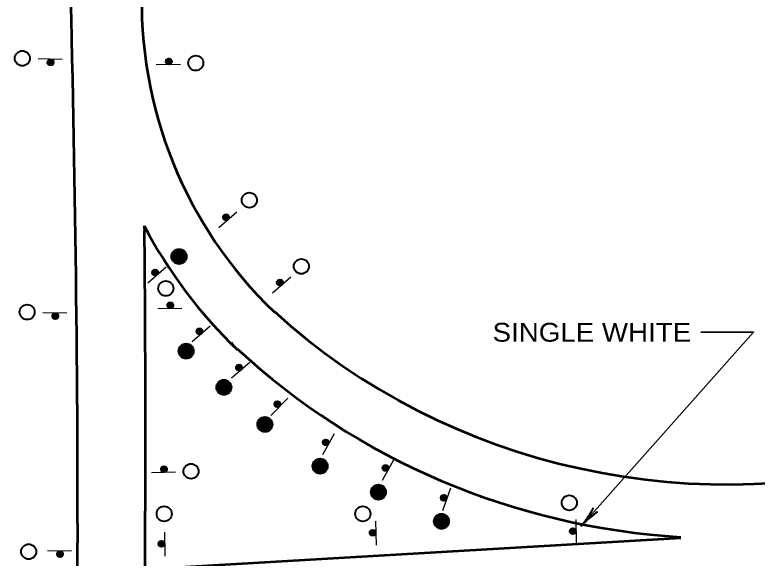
# Model space of a CAD drawing. Extents: x 393 to 1249, y -102 to 530.
# Drawn here: x 863.4 to 959.2, y 159 to 229.1 of the extents above; entities that cross this region are included whole.
import ezdxf
from ezdxf.enums import TextEntityAlignment as Align

# ---------------------------------------------------------------- set-up
doc = ezdxf.new("R2010")
doc.units = 0
doc.header["$LTSCALE"] = 0.97
doc.layers.add('1', color=7, linetype='Continuous', lineweight=40)
doc.layers.add('4', color=7, linetype='Continuous', lineweight=25)

msp = doc.modelspace()

# ---------------------------------------------------------------- linework, layer by layer
at = {"layer": '1', "lineweight": 53}
msp.add_line((880.2188, 157.5822), (949.3432, 161.6421), dxfattribs=at)
at = {"layer": '1', "lineweight": 35}
msp.add_lwpolyline([(951.9086, 188.1491), (958.7126, 188.1491), (936.4571, 163.1419)], dxfattribs=at)
at = {"layer": '1'}
for centre, radius in [((864.3972, 223.4812), 0.972), ((868.0362, 222.96), 0.3791), ((868.0164, 222.9409), 0.3402), ((868.046, 222.9696), 0.35), ((868.0459, 222.9598), 0.3305), ((868.0362, 222.96), 0.3013), ((868.0362, 222.96), 0.2819), ((868.0459, 222.9598), 0.2722), ((868.0459, 222.9598), 0.2527), ((868.0457, 222.9501), 0.2335), ((868.0455, 222.9404), 0.2138), ((868.0455, 222.9404), 0.1944), ((868.0653, 222.9595), 0.1555), ((883.2842, 223.0824), 0.3791), ((883.2645, 223.1015), 0.3402), ((883.2941, 223.0729), 0.35), ((883.294, 223.0826), 0.3305), ((883.2842, 223.0824), 0.3013), ((883.2842, 223.0824), 0.2819), ((883.294, 223.0826), 0.2722), ((883.294, 223.0826), 0.2527), ((883.2938, 223.0923), 0.2335), ((883.2936, 223.102), 0.2138), ((883.2936, 223.102), 0.1944), ((883.2933, 223.1215), 0.175), ((883.1475, 223.1189), 0.00972), ((883.3025, 223.1508), 0.1461), ((883.3124, 223.1412), 0.1555), ((883.3134, 223.0829), 0.1555), ((883.312, 223.1607), 0.1166), ((883.3037, 223.0827), 0.1069), ((883.3119, 223.1704), 0.0977), ((883.3117, 223.1801), 0.0778), ((883.3114, 223.1995), 0.0583), ((883.311, 223.219), 0.0389), ((883.3107, 223.2384), 0.0194), ((886.761, 222.8713), 0.972), ((868.0452, 222.921), 0.175), ((867.8994, 222.9235), 0.00972), ((868.0544, 222.8916), 0.1461), ((868.0643, 222.9012), 0.1555), ((868.064, 222.8818), 0.1166), ((868.0556, 222.9597), 0.1069), ((868.0638, 222.872), 0.0977), ((868.0636, 222.8623), 0.0778), ((868.0633, 222.8429), 0.0583), ((868.0629, 222.8234), 0.0389), ((868.0626, 222.804), 0.0194), ((893.6735, 205.1835), 0.972), ((890.6821, 202.9709), 0.3791), ((890.6547, 202.9728), 0.3402), ((890.6958, 202.9699), 0.35), ((890.6894, 202.9772), 0.3305), ((890.6821, 202.9709), 0.3013), ((890.6821, 202.9709), 0.2819), ((890.6894, 202.9772), 0.2722), ((890.6894, 202.9772), 0.2527), ((890.6831, 202.9846), 0.2335), ((890.6767, 202.9919), 0.2138), ((890.6767, 202.9919), 0.1944), ((890.6639, 203.0066), 0.175), ((890.6521, 203.035), 0.1461), ((890.6659, 203.034), 0.1555), ((890.6531, 203.0487), 0.1166), ((890.7041, 202.99), 0.1555), ((890.6467, 203.056), 0.0977), ((890.6403, 203.0634), 0.0778), ((890.6276, 203.078), 0.0583), ((890.6148, 203.0927), 0.0389), ((890.6021, 203.1074), 0.0194), ((890.6968, 202.9836), 0.1069), ((890.5539, 202.9109), 0.00972), ((884.6005, 197.9154), 0.972), ((884.5874, 197.9582), 0.8529), ((884.5747, 197.9328), 0.7878), ((884.5874, 197.8946), 0.7017), ((884.5111, 197.6405), 0.6228), ((884.5747, 197.9709), 0.5846), ((884.7272, 197.7803), 0.6414), ((884.5493, 197.8946), 0.4322), ((884.6509, 197.8184), 0.5216), ((884.6001, 198.1488), 0.3831), ((884.5746, 197.9582), 0.3558), ((884.8288, 197.6786), 0.5762), ((884.168, 197.6913), 0.3923), ((884.6001, 197.9582), 0.2049), ((884.6001, 197.9328), 0.0508), ((900.3826, 196.6445), 0.972), ((881.5332, 195.8551), 0.3791), ((881.5058, 195.857), 0.3402), ((881.5469, 195.8541), 0.35), ((881.5406, 195.8615), 0.3305), ((881.5332, 195.8551), 0.3013), ((881.5332, 195.8551), 0.2819), ((881.5406, 195.8615), 0.2722), ((881.5406, 195.8615), 0.2527), ((881.5342, 195.8688), 0.2335), ((881.5278, 195.8761), 0.2138), ((881.5278, 195.8761), 0.1944), ((881.5151, 195.8908), 0.175), ((881.5033, 195.9192), 0.1461), ((881.517, 195.9182), 0.1555), ((881.5042, 195.9329), 0.1166), ((881.405, 195.7952), 0.00972), ((881.5552, 195.8742), 0.1555), ((881.4979, 195.9403), 0.0977), ((881.4915, 195.9476), 0.0778), ((881.4787, 195.9623), 0.0583), ((881.466, 195.9769), 0.0389), ((881.4532, 195.9916), 0.0194), ((881.5479, 195.8679), 0.1069), ((882.8982, 193.7983), 0.972), ((897.6194, 194.568), 0.3791), ((897.592, 194.57), 0.3402), ((897.6331, 194.5671), 0.35), ((897.6267, 194.5744), 0.3305), ((897.6194, 194.568), 0.3013), ((897.6194, 194.568), 0.2819), ((897.6267, 194.5744), 0.2722), ((897.6267, 194.5744), 0.2527), ((897.6204, 194.5818), 0.2335), ((897.614, 194.5891), 0.2138), ((897.614, 194.5891), 0.1944), ((897.6012, 194.6038), 0.175), ((897.5894, 194.6321), 0.1461), ((897.6031, 194.6312), 0.1555), ((897.5904, 194.6459), 0.1166), ((897.4912, 194.5081), 0.00972), ((897.6414, 194.5872), 0.1555), ((897.584, 194.6532), 0.0977), ((897.5776, 194.6605), 0.0778), ((897.5649, 194.6752), 0.0583), ((897.5521, 194.6899), 0.0389), ((897.5394, 194.7045), 0.0194), ((897.6341, 194.5808), 0.1069), ((865.0071, 190.7486), 0.972), ((883.4841, 191.6155), 0.3791), ((883.4644, 191.6346), 0.3402), ((883.494, 191.606), 0.35), ((883.4939, 191.6157), 0.3305), ((883.4841, 191.6155), 0.3013), ((883.4841, 191.6155), 0.2819), ((883.4939, 191.6157), 0.2722), ((883.4939, 191.6157), 0.2527), ((883.4937, 191.6254), 0.2335), ((883.4935, 191.6352), 0.2138), ((883.4935, 191.6352), 0.1944), ((883.4932, 191.6546), 0.175), ((883.3474, 191.652), 0.00972), ((883.5024, 191.6839), 0.1461), ((883.5123, 191.6744), 0.1555), ((883.5133, 191.6161), 0.1555), ((883.5119, 191.6938), 0.1166), ((883.5036, 191.6159), 0.1069), ((883.5118, 191.7035), 0.0977), ((883.5116, 191.7132), 0.0778), ((883.5113, 191.7327), 0.0583), ((883.5109, 191.7521), 0.0389), ((883.5106, 191.7716), 0.0194), ((868.6461, 190.2275), 0.3791), ((868.6263, 190.2084), 0.3402), ((868.656, 190.2371), 0.35), ((868.6558, 190.2273), 0.3305), ((868.6461, 190.2275), 0.3013), ((868.6461, 190.2275), 0.2819), ((868.6558, 190.2273), 0.2722), ((868.6558, 190.2273), 0.2527), ((868.6556, 190.2176), 0.2335), ((868.6555, 190.2079), 0.2138), ((868.6555, 190.2079), 0.1944), ((868.6551, 190.1885), 0.175), ((868.5094, 190.191), 0.00972), ((868.6643, 190.1591), 0.1461), ((868.6742, 190.1687), 0.1555), ((868.6752, 190.227), 0.1555), ((868.6739, 190.1493), 0.1166), ((868.6655, 190.2272), 0.1069), ((868.6737, 190.1395), 0.0977), ((868.6736, 190.1298), 0.0778), ((868.6732, 190.1104), 0.0583), ((868.6729, 190.0909), 0.0389), ((868.6725, 190.0715), 0.0194), ((887.2507, 188.2655), 0.3791), ((887.2232, 188.2674), 0.3402), ((887.2644, 188.2646), 0.35), ((887.258, 188.2719), 0.3305), ((887.2507, 188.2655), 0.3013), ((887.2507, 188.2655), 0.2819), ((887.258, 188.2719), 0.2722), ((887.258, 188.2719), 0.2527), ((887.2516, 188.2792), 0.2335), ((887.2452, 188.2866), 0.2138), ((887.2452, 188.2866), 0.1944), ((887.2325, 188.3012), 0.175), ((887.2207, 188.3296), 0.1461), ((887.2344, 188.3287), 0.1555), ((887.2217, 188.3433), 0.1166), ((887.1225, 188.2056), 0.00972), ((887.2727, 188.2846), 0.1555), ((887.2153, 188.3507), 0.0977), ((887.2089, 188.358), 0.0778), ((887.1962, 188.3727), 0.0583), ((887.1834, 188.3873), 0.0389), ((887.1706, 188.402), 0.0194), ((887.2653, 188.2783), 0.1069), ((885.5154, 185.7169), 0.972), ((885.5023, 185.7596), 0.8529), ((885.0829, 185.4928), 0.3923), ((885.4896, 185.7342), 0.7878), ((885.5023, 185.6961), 0.7017), ((885.426, 185.442), 0.6228), ((885.4896, 185.7724), 0.5846), ((885.6421, 185.5818), 0.6414), ((885.4642, 185.6961), 0.4322), ((885.5658, 185.6199), 0.5216), ((885.515, 185.9503), 0.3831), ((885.4895, 185.7597), 0.3558), ((885.7437, 185.4801), 0.5762), ((885.515, 185.7597), 0.2049), ((885.515, 185.7342), 0.0508), ((892.3333, 183.5894), 0.3791), ((892.3059, 183.5913), 0.3402), ((892.347, 183.5884), 0.35), ((892.3407, 183.5958), 0.3305), ((892.3333, 183.5894), 0.3013), ((892.3333, 183.5894), 0.2819), ((892.3407, 183.5958), 0.2722), ((892.3407, 183.5958), 0.2527), ((892.3343, 183.6031), 0.2335), ((892.3279, 183.6104), 0.2138), ((892.3279, 183.6104), 0.1944), ((892.3152, 183.6251), 0.175), ((892.3034, 183.6535), 0.1461), ((892.3171, 183.6525), 0.1555), ((892.3043, 183.6672), 0.1166), ((892.2051, 183.5295), 0.00972), ((892.3553, 183.6085), 0.1555), ((892.298, 183.6745), 0.0977), ((892.2916, 183.6819), 0.0778), ((892.2788, 183.6965), 0.0583), ((892.2661, 183.7112), 0.0389), ((892.2533, 183.7259), 0.0194), ((892.348, 183.6021), 0.1069), ((890.3949, 181.0409), 0.972), ((890.3817, 181.0836), 0.8529), ((889.9624, 180.8168), 0.3923), ((890.369, 181.0582), 0.7878), ((890.3817, 181.0201), 0.7017), ((890.3055, 180.7659), 0.6228), ((890.369, 181.0963), 0.5846), ((890.5215, 180.9057), 0.6414), ((890.3436, 181.0201), 0.4322), ((890.4452, 180.9438), 0.5216), ((890.3944, 181.2742), 0.3831), ((890.369, 181.0836), 0.3558), ((890.6232, 180.8041), 0.5762), ((890.3945, 181.0836), 0.2049), ((890.3944, 181.0582), 0.0508), ((897.2897, 178.8669), 0.3791), ((897.2622, 178.8664), 0.3402), ((897.3034, 178.8671), 0.35), ((897.2964, 178.8739), 0.3305), ((897.2897, 178.8669), 0.3013), ((897.2897, 178.8669), 0.2819), ((897.2964, 178.8739), 0.2722), ((897.2964, 178.8739), 0.2527), ((897.2894, 178.8806), 0.2335), ((897.2824, 178.8874), 0.2138), ((897.2824, 178.8874), 0.1944), ((897.2685, 178.9009), 0.175), ((897.2542, 178.9281), 0.1461), ((897.268, 178.9283), 0.1555), ((897.254, 178.9419), 0.1166), ((897.247, 178.9486), 0.0977), ((897.3099, 178.8878), 0.1555), ((897.1672, 178.796), 0.00972), ((897.24, 178.9554), 0.0778), ((897.226, 178.9689), 0.0583), ((897.212, 178.9824), 0.0389), ((897.1981, 178.9959), 0.0194), ((897.3032, 178.8808), 0.1069), ((895.6808, 176.2631), 0.972), ((895.6677, 176.3058), 0.8529), ((895.2483, 176.039), 0.3923), ((895.655, 176.2804), 0.7878), ((895.6677, 176.2423), 0.7017), ((895.5915, 175.9882), 0.6228), ((895.655, 176.3186), 0.5846), ((895.8075, 176.1279), 0.6414), ((895.6296, 176.2423), 0.4322), ((895.7312, 176.166), 0.5216), ((895.6804, 176.4964), 0.3831), ((895.655, 176.3058), 0.3558), ((895.9091, 176.0263), 0.5762), ((895.6804, 176.3058), 0.2049), ((895.6804, 176.2804), 0.0508), ((903.5348, 173.9408), 0.3791), ((903.5084, 173.9332), 0.3402), ((903.548, 173.9446), 0.35), ((903.5395, 173.9493), 0.3305), ((903.5348, 173.9408), 0.3013), ((903.5348, 173.9408), 0.2819), ((903.5395, 173.9493), 0.2722), ((903.5395, 173.9493), 0.2527), ((903.531, 173.954), 0.2335), ((903.5225, 173.9587), 0.2138), ((903.5225, 173.9587), 0.1944), ((903.5055, 173.9681), 0.175), ((903.4847, 173.9908), 0.1461), ((903.498, 173.9945), 0.1555), ((903.481, 174.004), 0.1166), ((903.4725, 174.0087), 0.0977), ((903.464, 174.0134), 0.0778), ((903.447, 174.0228), 0.0583), ((903.43, 174.0322), 0.0389), ((903.549, 173.9663), 0.1555), ((903.413, 174.0417), 0.0194), ((903.4349, 173.8406), 0.00972), ((903.5443, 173.9578), 0.1069), ((902.7967, 170.8754), 0.972), ((902.7835, 170.9182), 0.8529), ((902.7709, 170.8928), 0.7878), ((902.7836, 170.8547), 0.7017), ((902.7709, 170.9309), 0.5846), ((902.7962, 171.1088), 0.3831), ((882.6709, 170.4715), 0.3791), ((882.6511, 170.4906), 0.3402), ((882.6808, 170.462), 0.35), ((882.6806, 170.4717), 0.3305), ((882.6709, 170.4715), 0.3013), ((882.6709, 170.4715), 0.2819), ((882.6806, 170.4717), 0.2722), ((882.6806, 170.4717), 0.2527), ((882.6804, 170.4814), 0.2335), ((882.6803, 170.4912), 0.2138), ((882.6803, 170.4912), 0.1944), ((882.6799, 170.5106), 0.175), ((882.5342, 170.508), 0.00972), ((882.6891, 170.5399), 0.1461), ((882.699, 170.5304), 0.1555), ((882.7, 170.4721), 0.1555), ((882.6987, 170.5498), 0.1166), ((882.6903, 170.4719), 0.1069), ((882.6985, 170.5595), 0.0977), ((882.6984, 170.5692), 0.0778), ((882.698, 170.5887), 0.0583), ((882.6977, 170.6081), 0.0389), ((882.6973, 170.6276), 0.0194), ((886.1511, 170.2146), 0.972), ((902.3642, 170.6513), 0.3923), ((902.7073, 170.6005), 0.6228), ((902.9233, 170.7403), 0.6414), ((902.7454, 170.8547), 0.4322), ((902.8471, 170.7784), 0.5216), ((902.7708, 170.9182), 0.3558), ((903.025, 170.6386), 0.5762), ((902.7963, 170.9182), 0.2049), ((902.7962, 170.8928), 0.0508), ((911.2465, 170.6392), 0.3791), ((911.22, 170.6317), 0.3402), ((911.2597, 170.643), 0.35), ((911.2512, 170.6477), 0.3305), ((911.2465, 170.6392), 0.3013), ((911.2465, 170.6392), 0.2819), ((911.2512, 170.6477), 0.2722), ((911.2512, 170.6477), 0.2527), ((911.2427, 170.6524), 0.2335), ((911.2342, 170.6572), 0.2138), ((911.2342, 170.6572), 0.1944), ((911.2172, 170.6666), 0.175), ((911.1964, 170.6892), 0.1461), ((911.2096, 170.693), 0.1555), ((911.1926, 170.7024), 0.1166), ((911.1841, 170.7071), 0.0977), ((911.1756, 170.7119), 0.0778), ((911.1586, 170.7213), 0.0583), ((911.1416, 170.7307), 0.0389), ((911.2606, 170.6647), 0.1555), ((911.1246, 170.7401), 0.0194), ((911.1465, 170.5391), 0.00972), ((911.2559, 170.6562), 0.1069), ((910.3191, 167.5208), 0.972), ((910.3059, 167.5635), 0.8529), ((909.8866, 167.2967), 0.3923), ((910.2932, 167.5382), 0.7878), ((910.306, 167.5), 0.7017), ((910.2297, 167.2459), 0.6228), ((910.2932, 167.5763), 0.5846), ((910.4457, 167.3857), 0.6414), ((910.2678, 167.5), 0.4322), ((910.3695, 167.4238), 0.5216), ((910.3186, 167.7542), 0.3831), ((910.2932, 167.5636), 0.3558), ((910.5474, 167.284), 0.5762), ((910.3187, 167.5636), 0.2049), ((910.3186, 167.5382), 0.0508), ((918.7443, 166.7835), 0.3791), ((918.7196, 166.7714), 0.3402), ((918.7567, 166.7895), 0.35), ((918.7475, 166.7927), 0.3305), ((918.7443, 166.7835), 0.3013), ((918.7443, 166.7835), 0.2819), ((918.7475, 166.7927), 0.2722), ((918.7475, 166.7927), 0.2527), ((918.7383, 166.7958), 0.2335), ((918.7291, 166.799), 0.2138), ((918.7291, 166.799), 0.1944), ((918.7107, 166.8053), 0.175), ((918.6863, 166.824), 0.1461), ((918.6987, 166.83), 0.1555), ((918.6803, 166.8364), 0.1166), ((918.6711, 166.8395), 0.0977), ((918.6619, 166.8427), 0.0778), ((918.6435, 166.849), 0.0583), ((918.6251, 166.8554), 0.0389), ((918.6068, 166.8617), 0.0194), ((918.7538, 166.8111), 0.1555), ((918.7506, 166.8019), 0.1069), ((918.6632, 166.6675), 0.00972), ((934.9449, 166.1484), 0.972), ((882.6948, 164.7253), 0.972), ((908.3117, 164.7253), 0.972), ((918.4514, 163.7596), 0.972), ((918.4382, 163.8023), 0.8529), ((918.0189, 163.5355), 0.3923), ((918.4256, 163.7769), 0.7878), ((918.4383, 163.7388), 0.7017), ((918.362, 163.4847), 0.6228), ((918.4256, 163.8151), 0.5846), ((918.578, 163.6244), 0.6414), ((918.4001, 163.7388), 0.4322), ((918.5018, 163.6625), 0.5216), ((918.451, 163.9929), 0.3831), ((918.4255, 163.8024), 0.3558), ((918.6797, 163.5228), 0.5762), ((918.451, 163.8024), 0.2049), ((918.451, 163.7769), 0.0508), ((935.4028, 162.4943), 0.3791), ((935.3837, 162.4745), 0.3402), ((935.4123, 162.5042), 0.35), ((935.4026, 162.504), 0.3305), ((935.4028, 162.4943), 0.3013), ((935.4028, 162.4943), 0.2819), ((935.4026, 162.504), 0.2722), ((909.5827, 162.2909), 0.3791), ((909.5636, 162.2711), 0.3402), ((909.5923, 162.3008), 0.35), ((909.5825, 162.3006), 0.3305), ((909.5827, 162.2909), 0.3013), ((909.5827, 162.2909), 0.2819), ((909.5825, 162.3006), 0.2722), ((909.5825, 162.3006), 0.2527), ((909.5728, 162.3004), 0.2335), ((909.5631, 162.3003), 0.2138), ((909.5143, 162.3091), 0.1461), ((909.5239, 162.319), 0.1555), ((909.5631, 162.3003), 0.1944), ((909.5437, 162.2999), 0.175), ((909.5045, 162.3187), 0.1166), ((909.4947, 162.3185), 0.0977), ((909.485, 162.3183), 0.0778), ((909.4461, 162.3177), 0.0389), ((909.4656, 162.318), 0.0583), ((909.4267, 162.3173), 0.0194), ((909.5822, 162.32), 0.1555), ((909.5824, 162.3103), 0.1069), ((909.5462, 162.1541), 0.00972), ((935.4026, 162.504), 0.2527), ((935.3929, 162.5038), 0.2335), ((935.3832, 162.5036), 0.2138), ((935.3344, 162.5125), 0.1461), ((935.3439, 162.5224), 0.1555), ((935.3637, 162.5033), 0.175), ((935.3832, 162.5036), 0.1944), ((935.3245, 162.5221), 0.1166), ((935.3148, 162.5219), 0.0977), ((935.3051, 162.5217), 0.0778), ((935.2856, 162.5214), 0.0583), ((935.2662, 162.521), 0.0389), ((935.2468, 162.5207), 0.0194), ((935.4023, 162.5234), 0.1555), ((935.4024, 162.5137), 0.1069), ((935.3663, 162.3575), 0.00972), ((882.3395, 160.8678), 0.3791), ((882.3204, 160.848), 0.3402), ((882.349, 160.8777), 0.35), ((882.3393, 160.8775), 0.3305), ((882.3395, 160.8678), 0.3013), ((882.3395, 160.8678), 0.2819), ((882.3393, 160.8775), 0.2722), ((882.3393, 160.8775), 0.2527), ((882.3296, 160.8773), 0.2335), ((882.3199, 160.8772), 0.2138), ((882.2711, 160.886), 0.1461), ((882.2807, 160.8959), 0.1555), ((882.3199, 160.8772), 0.1944), ((882.3005, 160.8768), 0.175), ((882.2612, 160.8956), 0.1166), ((882.2515, 160.8954), 0.0977), ((882.2418, 160.8952), 0.0778), ((882.2029, 160.8946), 0.0389), ((882.2224, 160.8949), 0.0583), ((882.1835, 160.8942), 0.0194), ((882.339, 160.8969), 0.1555), ((882.3392, 160.8872), 0.1069), ((865.2104, 159.8458), 0.972), ((869.256, 159.528), 0.3791), ((882.303, 160.7311), 0.00972), ((869.2362, 159.5089), 0.3402), ((869.2659, 159.5376), 0.35), ((869.2657, 159.5279), 0.3305), ((869.256, 159.528), 0.3013), ((869.256, 159.528), 0.2819), ((869.2657, 159.5279), 0.2722), ((869.2657, 159.5279), 0.2527), ((869.2656, 159.5181), 0.2335), ((869.2654, 159.5084), 0.2138), ((869.2654, 159.5084), 0.1944), ((869.2651, 159.489), 0.175), ((869.1193, 159.4915), 0.00972), ((869.2743, 159.4597), 0.1461), ((869.2842, 159.4692), 0.1555), ((869.2852, 159.5275), 0.1555), ((869.2838, 159.4498), 0.1166), ((869.2755, 159.5277), 0.1069), ((869.2837, 159.44), 0.0977), ((869.2835, 159.4303), 0.0778), ((869.2831, 159.4109), 0.0583), ((869.2828, 159.3915), 0.0389), ((869.2825, 159.372), 0.0194)]:
    msp.add_circle(centre, radius, dxfattribs=at)
at = {"layer": '1', "lineweight": 53}
for centre, radius, start, end in [((-1822.5792, 162.2285), 2694.1082, 358.26332, 1.73668), ((935.2205, 230.8084), 55.4409, 177.69851, 226.22678), ((898.007, 202.8022), 17.9227, 182.96106, 185.00425), ((935.2205, 230.8084), 62.2449, 207.69798, 226.22678), ((-1822.5792, 175.3186), 2702.8562, 359.62402, 0.54947), ((895.0122, 189.1948), 4.3809, 213.01714, 227.86622)]:
    msp.add_arc(centre, radius, start, end, dxfattribs=at)
for major_axis, ratio, start_param, end_param in [((-80.225, 11.5377), 0.914497, 0.9311997, 3.1747556), ((-86.4787, 12.4371), 0.928319, 0.9272378, 1.6585366)]:
    msp.add_ellipse((953.2504, 242.7846), major_axis=major_axis, ratio=ratio, start_param=start_param, end_param=end_param, dxfattribs=at)
at = {"layer": '1'}
for centre, major_axis, ratio, start_param, end_param in [((936.9616, 164.1127), (-1.0405, -1.3975), 0.122415, 0.8963533, 3.1415927), ((937.3348, 163.8187), (1.2626, 1.1618), 0.07063, 6.2823074, 8.5597026)]:
    msp.add_ellipse(centre, major_axis=major_axis, ratio=ratio, start_param=start_param, end_param=end_param, dxfattribs=at)
at = {"layer": '4'}
for p, q in [((869.5303, 223.3422), (866.42, 223.3965)), ((884.7784, 222.7001), (881.6681, 222.6459)), ((892.0724, 203.6384), (889.7246, 201.5977)), ((882.9235, 196.5226), (880.5757, 194.4819)), ((899.0096, 195.2356), (896.662, 193.1949)), ((870.1402, 190.6098), (867.0299, 190.664)), ((884.9782, 191.2332), (881.8678, 191.179)), ((888.6409, 188.9331), (886.2932, 186.8922)), ((893.7235, 184.257), (891.3759, 182.2161)), ((898.6165, 179.6531), (896.4555, 177.4154)), ((904.6128, 175.0436), (903.1048, 172.3229)), ((912.3246, 171.7421), (910.8164, 169.0214)), ((884.165, 170.0892), (881.0546, 170.0351)), ((919.6145, 168.0568), (918.6017, 165.1154)), ((909.9649, 163.7849), (910.0192, 160.6746)), ((935.785, 163.9883), (935.8393, 160.878)), ((882.7218, 162.3618), (882.776, 159.2515)), ((870.7501, 159.9103), (867.6398, 159.9645))]:
    msp.add_line(p, q, dxfattribs=at)
for centre in [(868.0264, 222.9602), (883.2745, 223.0822), (890.6748, 202.9645), (881.5259, 195.8487), (897.6121, 194.5617), (883.4744, 191.6154), (868.6364, 190.2277), (887.2433, 188.2591), (892.326, 183.583), (897.2829, 178.8599), (903.5301, 173.9323), (882.6612, 170.4714), (911.2418, 170.6307), (918.7411, 166.7743), (935.4029, 162.4845), (909.5829, 162.2812), (882.3397, 160.8581), (869.2463, 159.5282)]:
    msp.add_circle(centre, 0.3985, dxfattribs=at)

# ---------------------------------------------------------------- texts
at = {"layer": '1', "width": 1.1}
msp.add_text('SINGLE WHITE', height=2.43, dxfattribs=at).set_placement((937.8559, 186.93), align=Align.CENTER)

doc.saveas('drawing.dxf')
